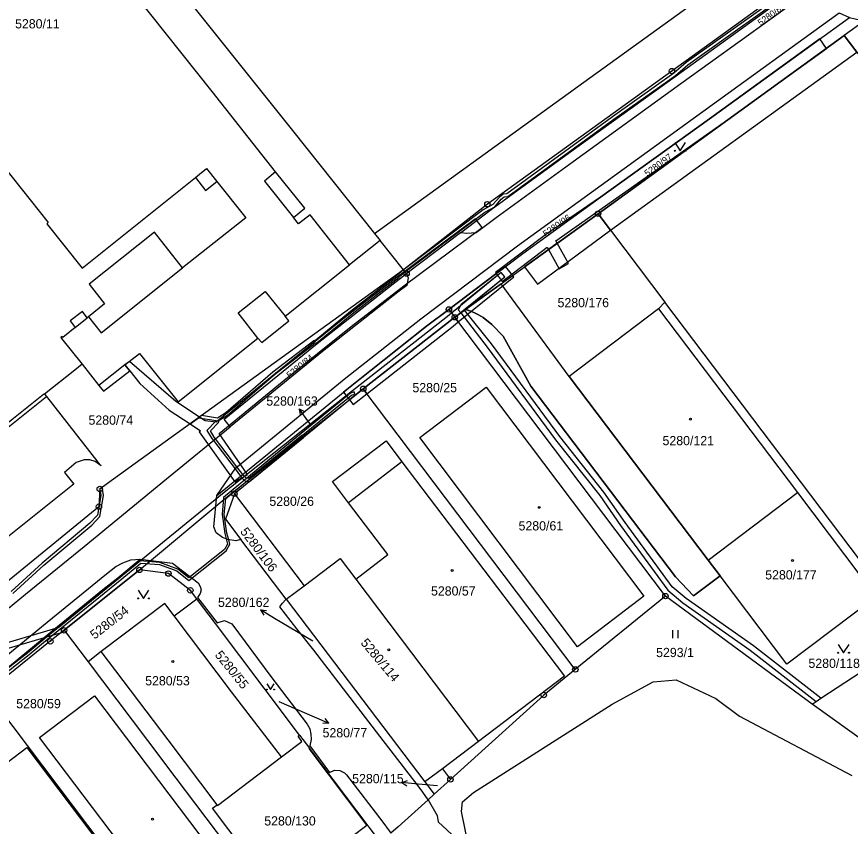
# Model space of a CAD drawing. Extents: x -644096 to -634268, y -1141430 to -1133463.
# Drawn here: x -637778.1 to -637624.4, y -1140072.9 to -1139923.7 of the extents above; entities that cross this region are included whole.
import ezdxf

# ---------------------------------------------------------------- set-up
doc = ezdxf.new("R2010")
doc.units = 0
for name, color, linetype in [('_CIVIL_CONSTRUCTION', 7, 'Continuous'), ('B_Hranice _3D', 7, 'Continuous'), ('M_Svah_Nasyp', 7, 'Continuous'), ('M_Svah_Zarez', 7, 'Continuous'), ('svrsek_osa_sjezdy', 7, 'Continuous'), ('svrsek_osa_VRT', 7, 'Continuous'), ('svrsek_popisy_VRT', 7, 'Continuous'), ('terminal_VRT', 7, 'Continuous')]:
    doc.layers.add(name, color=color, linetype=linetype)

msp = doc.modelspace()

# ---------------------------------------------------------------- linework, layer by layer
at = {"layer": '_CIVIL_CONSTRUCTION'}
for centre, radius in [((-637657.31, -1139933.74), 0.5), ((-637657.31, -1139933.74), 0.0303), ((-637691.33, -1139958.27), 0.5), ((-637691.33, -1139958.27), 0.0303), ((-637670.92, -1139960.03), 0.5), ((-637670.92, -1139960.03), 0.0303), ((-637706.23, -1139971.06), 0.5), ((-637706.23, -1139971.06), 0.0303), ((-637698.43, -1139977.67), 0.5), ((-637698.43, -1139977.67), 0.0303), ((-637697.34, -1139979.11), 0.5), ((-637697.34, -1139979.11), 0.0303), ((-637714.22, -1139992.29), 0.5), ((-637714.22, -1139992.29), 0.0303), ((-637762.79, -1140010.76), 0.5), ((-637762.79, -1140010.76), 0.0303), ((-637737.95, -1140011.63), 0.5), ((-637737.95, -1140011.63), 0.0303), ((-637762.94, -1140014.01), 0.5), ((-637762.94, -1140014.01), 0.0303), ((-637755.47, -1140025.67), 0.5), ((-637755.47, -1140025.67), 0.0303), ((-637750.13, -1140026.34), 0.5), ((-637750.13, -1140026.34), 0.0303), ((-637746.09, -1140029.43), 0.5), ((-637746.09, -1140029.43), 0.0303), ((-637658.5, -1140030.49), 0.5), ((-637658.5, -1140030.49), 0.0303), ((-637769.36, -1140036.79), 0.5), ((-637769.36, -1140036.79), 0.0303), ((-637771.9, -1140038.82), 0.5), ((-637771.9, -1140038.82), 0.0303), ((-637675.12, -1140044), 0.5), ((-637675.12, -1140044), 0.0303), ((-637680.93, -1140048.72), 0.5), ((-637680.93, -1140048.72), 0.0303), ((-637698.14, -1140064.28), 0.5), ((-637698.14, -1140064.28), 0.0303)]:
    msp.add_circle(centre, radius, dxfattribs=at)
at = {"layer": 'B_Hranice _3D'}
for points in [[(-637626.38, -1139912), (-637654.66, -1139932.19), (-637656.97, -1139934.15), (-637668.29, -1139942.19), (-637687.77, -1139956.35), (-637688.44, -1139956.44), (-637689.11, -1139956.96), (-637690.3, -1139958.33), (-637692.1, -1139959.33), (-637706.78, -1139970.37), (-637708, -1139971.4), (-637716.58, -1139978.05), (-637722.97, -1139983.33), (-637723.33, -1139983.47), (-637730.87, -1139989.25), (-637739.55, -1139996.73), (-637741.07, -1139997.68), (-637744.01, -1139997.22), (-637744.59, -1139997.64), (-637741.33, -1139998.14), (-637741.36, -1139998.24), (-637743.02, -1139999.96), (-637742.11, -1140001.47), (-637741.85, -1140001.82), (-637737.85, -1140007.05), (-637736.82, -1140008.39), (-637736.7, -1140008.55), (-637736.06, -1140009.22), (-637735.16, -1140009.36), (-637725.24, -1140001.27), (-637725.55, -1140000.88), (-637735.3, -1140008.83), (-637735.82, -1140008.75), (-637736.32, -1140008.23), (-637736.44, -1140008.07), (-637737.5, -1140006.68), (-637741.46, -1140001.5), (-637741.69, -1140001.19), (-637742.4, -1140000.04), (-637740.9, -1139998.5), (-637740.8, -1139998.1), (-637739.25, -1139997.13), (-637730.55, -1139989.63), (-637723.09, -1139983.91), (-637722.71, -1139983.77), (-637716.26, -1139978.45)], [(-637716.26, -1139978.45), (-637707.66, -1139971.76), (-637706.47, -1139970.76), (-637691.82, -1139959.75), (-637689.98, -1139958.73), (-637688.77, -1139957.32), (-637688.24, -1139956.92), (-637687.57, -1139956.83), (-637667.99, -1139942.59), (-637656.67, -1139934.55), (-637654.36, -1139932.59), (-637626.1, -1139912.4)], [(-637780.44, -1140044.91), (-637775.79, -1140041.27), (-637772.41, -1140038.42), (-637758.71, -1140027.31), (-637755.23, -1140024.4), (-637751.79, -1140024.67), (-637748.57, -1140025.86), (-637746.37, -1140027.62), (-637739.49, -1140022.17), (-637738.79, -1140020.95), (-637739.02, -1140020.11), (-637739.34, -1140018.9), (-637739.85, -1140015.44), (-637739.57, -1140012.52), (-637729.09, -1140003.85), (-637716.38, -1139993.45), (-637715.78, -1139993.26), (-637715.9, -1139992.88), (-637716.58, -1139993.09), (-637729.35, -1140003.55), (-637739.95, -1140012.32), (-637740.25, -1140015.46), (-637739.74, -1140018.98), (-637739.4, -1140020.21), (-637739.21, -1140020.89), (-637739.79, -1140021.91), (-637746.37, -1140027.1), (-637748.37, -1140025.5), (-637751.71, -1140024.27), (-637755.37, -1140023.98), (-637758.97, -1140027.01), (-637772.67, -1140038.12), (-637776.05, -1140040.95), (-637780.7, -1140044.59)], [(-637778.79, -1140030.04), (-637773.09, -1140024.82), (-637764.26, -1140017.4), (-637762.75, -1140015.82), (-637762.08, -1140011.97), (-637762.34, -1140010.44), (-637762.79, -1140010.76), (-637762.58, -1140011.97), (-637763.21, -1140015.58), (-637764.6, -1140017.04), (-637773.41, -1140024.44), (-637779.11, -1140029.66)]]:
    msp.add_lwpolyline(points, dxfattribs=at)
for points in [[(-637625.55, -1139927.19), (-637670.92, -1139960.03), (-637668.61, -1139963.08), (-637623.24, -1139930.24)], [(-637689.82, -1139970.89), (-637689.69, -1139971.06), (-637688.6, -1139972.49), (-637680.34, -1139966.2), (-637680.09, -1139966.65), (-637678.46, -1139965.47), (-637678.72, -1139965), (-637646.61, -1139942.44), (-637628.82, -1139929.56), (-637630.04, -1139927.83), (-637650.39, -1139942.52), (-637670.45, -1139957), (-637680.62, -1139963.89)], [(-637744.4, -1139997.51), (-637746.14, -1139998.76), (-637744.22, -1140000.03), (-637744.48, -1140000.22), (-637737.9, -1140009.44), (-637735.53, -1140008.08), (-637740.78, -1140000.55), (-637729.15, -1139991), (-637716.42, -1139980.8), (-637706.75, -1139973.33), (-637692.32, -1139962.59), (-637693.52, -1139960.99), (-637707.97, -1139971.75), (-637717.64, -1139979.22), (-637730.41, -1139989.46), (-637741.34, -1139998.41), (-637743.38, -1139998.19)], [(-637684.47, -1139969.81), (-637682.11, -1139973.02), (-637668.61, -1139963.08), (-637670.92, -1139960.03)], [(-637678.46, -1139965.47), (-637680.09, -1139966.65), (-637678.11, -1139970.19), (-637676.37, -1139969.21)], [(-637687.97, -1139969.76), (-637698.43, -1139977.67), (-637702.53, -1139980.77), (-637717.86, -1139992.91), (-637716.74, -1139994.34), (-637714.22, -1139992.29), (-637697.34, -1139979.11), (-637696.7, -1139979.95), (-637686.43, -1139971.67), (-637686.66, -1139971.39)], [(-637799.89, -1140046.07), (-637769.87, -1140037.2), (-637769.36, -1140036.79), (-637755.47, -1140025.67), (-637739.54, -1140012.41), (-637714.22, -1139992.29), (-637697.34, -1139979.11), (-637688.13, -1139971.63), (-637688.81, -1139970.89), (-637698.96, -1139979.2), (-637716.21, -1139992.69), (-637740.16, -1140011.63), (-637770.35, -1140036.3), (-637800.57, -1140045.22)], [(-637696.19, -1139976.76), (-637696.69, -1139977.75), (-637696.25, -1139978.32), (-637695.54, -1139977.81), (-637695.57, -1139977.77), (-637688.13, -1139971.63), (-637688.81, -1139970.89)], [(-637695.37, -1139977.69), (-637694.77, -1139977.86), (-637693.85, -1139978.23), (-637692.97, -1139978.64), (-637692.09, -1139979.15), (-637690.53, -1139980.42), (-637688.41, -1139982.57), (-637683.3, -1139991.78), (-637656.67, -1140026.92), (-637653.33, -1140030.42), (-637648.43, -1140026.77), (-637650.63, -1140023.86), (-637676.25, -1139990.02), (-637688.77, -1139972.92)], [(-637696.25, -1139978.32), (-637691.36, -1139984.62), (-637678.75, -1140001.69), (-637670.63, -1140011.94), (-637666.8, -1140017.46), (-637658.05, -1140029.4), (-637655.27, -1140031.76), (-637642.87, -1140040.47), (-637630.74, -1140049.9), (-637629.86, -1140049.32), (-637642.27, -1140039.67), (-637654.69, -1140030.94), (-637657.29, -1140028.76), (-637665.96, -1140016.9), (-637669.85, -1140011.32), (-637677.97, -1140001.07), (-637690.56, -1139984), (-637695.54, -1139977.81)], [(-637713.53, -1139993.21), (-637697.65, -1139980.72), (-637696.7, -1139979.95), (-637697.34, -1139979.11), (-637714.22, -1139992.29)], [(-637749.97, -1139996.21), (-637746.14, -1139998.76), (-637744.4, -1139997.51), (-637748.75, -1139994.61), (-637757.3, -1139987.23), (-637758.16, -1139987.9), (-637757.25, -1139989), (-637755.42, -1139991.32)], [(-637716.06, -1139995.2), (-637713.53, -1139993.21), (-637714.22, -1139992.29), (-637716.74, -1139994.34)]]:
    msp.add_lwpolyline(points, close=True, dxfattribs=at)
at = {"layer": 'M_Svah_Nasyp'}
for p, q in [((-637744.43, -1139952.76), (-637743.11, -1139951.71)), ((-637743.11, -1139951.71), (-637741.23, -1139954.12)), ((-637745.16, -1139953.36), (-637744.43, -1139952.76)), ((-637730.36, -1139952.34), (-637732.44, -1139954)), ((-637732.44, -1139954), (-637727.06, -1139960.74)), ((-637762.5, -1139981.97), (-637747.51, -1139969.98)), ((-637737.29, -1139978.29), (-637732.29, -1139974.35)), ((-637732.29, -1139974.35), (-637728.62, -1139978.92)), ((-637767.34, -1139981.01), (-637765.08, -1139979.22)), ((-637764.84, -1139979.04), (-637762.5, -1139981.97)), ((-637733.63, -1139982.94), (-637737.29, -1139978.29)), ((-637758.16, -1139987.9), (-637762.93, -1139991.7)), ((-637772.99, -1139993.25), (-637772.61, -1139993.74)), ((-637707.08, -1140005.77), (-637716.95, -1140013.28))]:
    msp.add_line(p, q, dxfattribs=at)
at = {"layer": 'M_Svah_Zarez'}
for centre in [(-637653.91, -1139997.87), (-637681.76, -1140014.14), (-637635.09, -1140023.92), (-637697.84, -1140025.79), (-637709.52, -1140040.39), (-637749.32, -1140042.55), (-637753.07, -1140071.59)]:
    msp.add_circle(centre, 0.175, dxfattribs=at)
at = {"layer": 'svrsek_osa_sjezdy'}
for p, q in [((-637657.14, -1140038.26), (-637657.14, -1140036.76)), ((-637656.14, -1140038.26), (-637656.14, -1140036.76))]:
    msp.add_line(p, q, dxfattribs=at)
for points in [[(-637656.79, -1139946.92), (-637655.79, -1139948.42), (-637654.79, -1139946.92)], [(-637755.72, -1140029.42), (-637754.72, -1140030.92), (-637753.72, -1140029.42)], [(-637626.66, -1140039.43), (-637625.66, -1140040.93), (-637624.66, -1140039.43)], [(-637732, -1140046.68), (-637731.32, -1140047.7), (-637730.64, -1140046.68)]]:
    msp.add_lwpolyline(points, dxfattribs=at)
for centre, radius in [((-637656.79, -1139948.42), 0.1), ((-637654.79, -1139948.42), 0.1), ((-637755.72, -1140030.92), 0.1), ((-637753.72, -1140030.92), 0.1), ((-637626.66, -1140040.93), 0.1), ((-637624.66, -1140040.93), 0.1), ((-637732, -1140047.7), 0.068), ((-637730.64, -1140047.7), 0.068)]:
    msp.add_circle(centre, radius, dxfattribs=at)
at = {"layer": 'svrsek_popisy_VRT'}
for p, q in [((-637724.26, -1139998.41), (-637726.02, -1139995.98)), ((-637726.02, -1139995.98), (-637725.03, -1139996.5)), ((-637726.02, -1139995.98), (-637725.84, -1139997.09)), ((-637724, -1139998.77), (-637724.26, -1139998.41)), ((-637730.56, -1140034.59), (-637733.13, -1140033.04)), ((-637733.13, -1140033.04), (-637732.02, -1140033.13)), ((-637733.13, -1140033.04), (-637732.53, -1140033.99)), ((-637723.49, -1140038.8), (-637730.56, -1140034.59)), ((-637729.75, -1140049.94), (-637723.29, -1140052.71)), ((-637723.29, -1140052.71), (-637720.53, -1140053.88)), ((-637720.53, -1140053.88), (-637721.25, -1140053.03)), ((-637720.53, -1140053.88), (-637721.65, -1140053.95)), ((-637707.11, -1140064.86), (-637706.07, -1140064.45)), ((-637704.12, -1140065.12), (-637707.11, -1140064.86)), ((-637707.11, -1140064.86), (-637706.16, -1140065.45)), ((-637700.53, -1140065.43), (-637704.12, -1140065.12))]:
    msp.add_line(p, q, dxfattribs=at)
at = {"layer": 'terminal_VRT'}
for p, q in [((-637621.84, -1139924.51), (-637625.55, -1139927.19)), ((-637670.92, -1139960.03), (-637625.55, -1139927.19)), ((-637625.55, -1139927.19), (-637612.98, -1139943.8)), ((-637695.37, -1139977.69), (-637670.92, -1139960.03)), ((-637670.92, -1139960.03), (-637658.61, -1139976.31)), ((-637712.12, -1139963.68), (-637711.11, -1139964.94)), ((-637711.11, -1139964.94), (-637716.72, -1139969.42)), ((-637706.78, -1139970.37), (-637711.11, -1139964.94)), ((-637706.23, -1139971.06), (-637706.78, -1139970.37)), ((-637658.61, -1139976.31), (-637659.77, -1139977.56)), ((-637612.18, -1140037.72), (-637658.61, -1139976.31)), ((-637698.43, -1139977.67), (-637697.34, -1139979.11)), ((-637697.34, -1139979.11), (-637695.37, -1139977.69)), ((-637659.77, -1139977.56), (-637634.18, -1140011.4)), ((-637697.34, -1139979.11), (-637714.22, -1139992.29)), ((-637658.5, -1140030.49), (-637697.34, -1139979.11)), ((-637714.22, -1139992.29), (-637737.95, -1140011.63)), ((-637675.12, -1140044), (-637714.22, -1139992.29)), ((-637737.95, -1140011.63), (-637725.13, -1140028.58)), ((-637650.63, -1140023.86), (-637634.18, -1140011.4)), ((-637728.43, -1140031.07), (-637736.81, -1140020.03)), ((-637650.63, -1140023.86), (-637648.43, -1140026.77)), ((-637715.6, -1140027.34), (-637692.94, -1140057.3)), ((-637728.43, -1140031.07), (-637725.13, -1140028.58)), ((-637749.1, -1140034.14), (-637744.91, -1140030.99)), ((-637728.43, -1140031.07), (-637702.88, -1140064.74)), ((-637658.5, -1140030.49), (-637675.12, -1140044)), ((-637631.47, -1140050.38), (-637658.5, -1140030.49)), ((-637769.36, -1140036.79), (-637764.95, -1140042.62)), ((-637629.86, -1140049.32), (-637612.18, -1140037.72)), ((-637762.51, -1140040.68), (-637764.95, -1140042.62)), ((-637783.61, -1140048.2), (-637742.13, -1140103.04)), ((-637613.75, -1140063.13), (-637631.47, -1140050.38)), ((-637725.94, -1140056.09), (-637724.13, -1140058.48)), ((-637692.94, -1140057.3), (-637699.63, -1140062.31)), ((-637711.01, -1140075.83), (-637724.13, -1140058.48)), ((-637699.63, -1140062.31), (-637702.88, -1140064.74)), ((-637699.63, -1140062.31), (-637698.14, -1140064.28)), ((-637698.14, -1140064.28), (-637701.16, -1140067.01)), ((-637702.88, -1140064.74), (-637701.16, -1140067.01)), ((-637701.16, -1140067.01), (-637702.26, -1140068.01))]:
    msp.add_line(p, q, dxfattribs=at)
for points in [[(-637563.31, -1139859.73), (-637606.05, -1139890.66), (-637603.12, -1139894.71), (-637624.44, -1139910), (-637657.31, -1139933.74), (-637691.33, -1139958.27), (-637706.78, -1139970.37)], [(-637785.99, -1139871.17), (-637767.92, -1139893.81), (-637748.41, -1139918.24), (-637727.28, -1139944.7), (-637712.12, -1139963.68)], [(-637716.72, -1139969.42), (-637724.03, -1139960.26), (-637726.12, -1139961.91), (-637727.06, -1139960.74), (-637724.96, -1139959), (-637730.36, -1139952.34), (-637742.05, -1139937.53), (-637787.38, -1139880.71), (-637793.07, -1139885.25), (-637793.55, -1139884.78), (-637787.97, -1139880.31), (-637792.06, -1139875.21)], [(-637696.28, -1139963.54), (-637690.61, -1139959.25), (-637674.44, -1139947.46), (-637656.73, -1139934.73), (-637623.8, -1139910.91), (-637590.73, -1139887.03), (-637578.64, -1139878.33)], [(-637578.64, -1139878.33), (-637578.74, -1139879.67), (-637579.14, -1139880.88), (-637589.62, -1139888.43), (-637622.83, -1139912.45), (-637655.64, -1139936.08), (-637675.49, -1139950.48), (-637689.7, -1139960.76), (-637693.39, -1139963.56), (-637695.12, -1139963.7), (-637696.28, -1139963.54)], [(-637712.12, -1139963.68), (-637673.58, -1139935.78), (-637648.87, -1139917.91), (-637605.89, -1139886.8), (-637610.08, -1139881.37), (-637611.46, -1139878.83)], [(-637741.21, -1140011.97), (-637737.73, -1140006.87), (-637717.41, -1139990.27), (-637703.62, -1139979.41), (-637685.77, -1139965.92), (-637672.15, -1139956.04), (-637651.6, -1139941.17), (-637626.45, -1139923.02), (-637624.56, -1139923.88)], [(-637698.43, -1139977.67), (-637684.78, -1139967.35), (-637670.45, -1139957), (-637650.39, -1139942.52), (-637624.56, -1139923.88)], [(-637624.56, -1139923.88), (-637622.49, -1139924.35), (-637621.84, -1139924.51)], [(-637787.32, -1139942.88), (-637772.31, -1139961.66), (-637772.55, -1139961.92), (-637766.05, -1139970.07), (-637745.16, -1139953.36), (-637743.28, -1139955.72), (-637741.23, -1139954.12), (-637735.88, -1139960.76), (-637747.51, -1139969.98), (-637752.69, -1139963.41), (-637764.76, -1139972.98), (-637761.89, -1139976.63), (-637764.84, -1139979.04), (-637765.08, -1139979.22), (-637765.98, -1139978.02), (-637768.26, -1139979.79), (-637767.34, -1139981.01), (-637769.59, -1139982.82), (-637769.7, -1139982.68), (-637769.94, -1139982.86), (-637769.85, -1139983), (-637766.06, -1139987.77)], [(-637696.28, -1139963.54), (-637706.12, -1139970.98), (-637706.23, -1139971.06)], [(-637801.31, -1140015.8), (-637800.91, -1140016.32), (-637772.61, -1139993.74), (-637763.13, -1140005.8), (-637762.54, -1140006.46), (-637763.62, -1140005.68), (-637764.62, -1140005.39), (-637765.66, -1140005.36), (-637767.13, -1140005.88), (-637769.28, -1140007.73), (-637767.54, -1140009.89), (-637767.79, -1140010.06), (-637799.19, -1140035.12), (-637808.83, -1140023.02), (-637812.28, -1140018.54), (-637839.95, -1139983.66), (-637852.33, -1139968.09)], [(-637706.78, -1139970.37), (-637752.95, -1140003.67), (-637761.33, -1140009.71), (-637762.79, -1140010.76), (-637762.94, -1140014.01), (-637800.78, -1140044.95)], [(-637766.06, -1139987.77), (-637762.93, -1139991.7), (-637762.1, -1139992.71), (-637757.25, -1139989), (-637758.16, -1139987.9), (-637755.46, -1139985.79), (-637748.36, -1139994.67), (-637733.63, -1139982.94), (-637732.88, -1139983.73), (-637727.94, -1139979.76), (-637728.62, -1139978.92), (-637716.72, -1139969.42)], [(-637738.74, -1139999.28), (-637739.84, -1139997.9), (-637722.69, -1139983.97), (-637708.69, -1139972.93), (-637706.23, -1139971.06)], [(-637706.23, -1139971.06), (-637705.93, -1139971.82), (-637706.18, -1139973.24), (-637707.84, -1139974.5), (-637721.74, -1139985.44), (-637738.74, -1139999.28)], [(-637741.21, -1140011.97), (-637716.55, -1139991.84), (-637702.53, -1139980.77), (-637698.43, -1139977.67)], [(-637648.43, -1140026.77), (-637653.33, -1140030.42), (-637656.67, -1140026.92), (-637683.3, -1139991.78), (-637688.41, -1139982.57), (-637690.53, -1139980.42), (-637692.09, -1139979.15), (-637692.97, -1139978.64), (-637693.85, -1139978.23), (-637694.77, -1139977.86), (-637695.37, -1139977.69)], [(-637659.77, -1139977.56), (-637676.25, -1139990.02), (-637650.63, -1140023.86)], [(-637766.06, -1139987.77), (-637767.41, -1139988.84), (-637772.99, -1139993.25), (-637773.13, -1139993.36), (-637779.01, -1139998.01), (-637781.96, -1140000.37)], [(-637691.54, -1139992.02), (-637662.47, -1140030.52), (-637674.7, -1140039.82), (-637703.81, -1140001.26), (-637691.54, -1139992.02)], [(-637845.37, -1140086.59), (-637832.39, -1140075.95), (-637810.87, -1140058.32), (-637793.23, -1140043.88), (-637776.46, -1140030.14), (-637765.68, -1140021.35), (-637750.47, -1140008.86), (-637738.74, -1139999.28)], [(-637715.6, -1140027.34), (-637709.68, -1140022.85), (-637716.95, -1140013.28), (-637719.87, -1140009.4), (-637709.96, -1140001.85), (-637707.08, -1140005.77), (-637684.44, -1140035.61), (-637677.14, -1140045.23), (-637692.94, -1140057.3)], [(-637736.81, -1140020.03), (-637737.69, -1140020.31), (-637739.23, -1140020.03), (-637740.17, -1140019.67), (-637741.3, -1140018.83), (-637741.78, -1140017.73), (-637741.21, -1140011.97)], [(-637737.95, -1140011.63), (-637739.63, -1140016.31), (-637736.81, -1140020.03)], [(-637634.18, -1140011.4), (-637619.69, -1140030.61), (-637636.14, -1140043.05), (-637648.43, -1140026.77)], [(-637817.35, -1140072.05), (-637807.11, -1140063.64), (-637789.18, -1140048.96), (-637772.5, -1140035.3), (-637761.56, -1140026.38), (-637759.83, -1140025.01), (-637758.55, -1140024.34), (-637757.04, -1140023.82), (-637755.35, -1140023.67)], [(-637817.35, -1140072.05), (-637816.23, -1140073.56), (-637805.85, -1140065.05), (-637788.02, -1140050.44), (-637771.25, -1140036.65), (-637762.25, -1140029.27), (-637759.48, -1140027.1), (-637755.35, -1140023.67)], [(-637755.35, -1140023.67), (-637749.35, -1140024.42), (-637744.64, -1140028.02), (-637744.26, -1140028.71), (-637744.09, -1140029.36), (-637744.26, -1140030.01), (-637744.77, -1140030.73), (-637741.17, -1140035.4), (-637739.81, -1140034.99), (-637738.41, -1140035.62), (-637731.25, -1140045.32), (-637724.55, -1140054.08), (-637724.09, -1140054.96), (-637723.86, -1140055.92), (-637723.81, -1140056.92), (-637724.07, -1140058.08), (-637720.43, -1140062.99), (-637719.53, -1140062.58), (-637718.55, -1140062.62), (-637717.68, -1140063.07), (-637717.32, -1140063.44), (-637710.62, -1140072.15), (-637709.44, -1140073.76), (-637709.14, -1140074.2)], [(-637725.13, -1140028.58), (-637718.46, -1140023.56), (-637715.6, -1140027.34)], [(-637744.91, -1140030.99), (-637746.09, -1140029.43), (-637750.13, -1140026.34), (-637755.47, -1140025.67), (-637769.36, -1140036.79)], [(-637749.1, -1140034.14), (-637750.81, -1140031.88), (-637762.51, -1140040.68)], [(-637725.94, -1140056.09), (-637732.47, -1140047.45), (-637741.48, -1140035.52), (-637744.78, -1140031.16), (-637744.91, -1140030.99)], [(-637702.26, -1140068.01), (-637703.23, -1140066.63), (-637704.1, -1140065.43), (-637711.15, -1140056.33), (-637723.35, -1140040.47), (-637726.44, -1140036.54), (-637729.58, -1140032.47), (-637729.19, -1140031.83), (-637728.43, -1140031.07)], [(-637729.29, -1140060.1), (-637738.49, -1140048.14), (-637749.1, -1140034.14)], [(-637769.36, -1140036.79), (-637771.9, -1140038.82), (-637783.61, -1140048.2)], [(-637741.17, -1140068.93), (-637750.17, -1140056.99), (-637762.51, -1140040.68)], [(-637764.95, -1140042.62), (-637759.67, -1140049.6), (-637751.15, -1140060.87), (-637750.67, -1140061.5), (-637728.34, -1140091.03)], [(-637675.12, -1140044), (-637680.93, -1140048.72), (-637698.14, -1140064.28)], [(-637702.26, -1140068.01), (-637700.61, -1140070.93), (-637700.39, -1140072.11), (-637694.64, -1140077.44), (-637696.09, -1140070.18), (-637695.9, -1140068.42), (-637693.88, -1140066.68), (-637668.35, -1140050.42), (-637660.75, -1140046.26), (-637656.5, -1140045.9), (-637649.2, -1140049.37), (-637644.85, -1140052.63), (-637624.17, -1140063.57)], [(-637744.59, -1140095.27), (-637773.88, -1140056.54), (-637763.73, -1140048.86), (-637734.44, -1140087.62), (-637744.59, -1140095.27)], [(-637631.47, -1140050.38), (-637630.74, -1140049.9), (-637629.86, -1140049.32)], [(-637729.29, -1140060.1), (-637725.53, -1140057.27), (-637726.23, -1140056.3), (-637725.94, -1140056.09)], [(-637786.36, -1140066.04), (-637776.22, -1140058.38), (-637746.95, -1140097.15), (-637757.1, -1140104.82), (-637786.36, -1140066.04)], [(-637724.13, -1140058.48), (-637724.25, -1140058.58), (-637713.56, -1140072.76), (-637730.14, -1140085.32), (-637742.03, -1140069.58), (-637741.17, -1140068.93)], [(-637741.17, -1140068.93), (-637741.08, -1140069.05), (-637729.29, -1140060.1)], [(-637702.26, -1140068.01), (-637707.79, -1140073.03), (-637709.14, -1140074.2)]]:
    msp.add_lwpolyline(points, dxfattribs=at)

# ---------------------------------------------------------------- texts
at = {"layer": 'svrsek_osa_VRT'}
for s, height, rotation, p in [('5280/85', 1.2, 36, (-637640.96, -1139925.46)), ('5280/97', 1.2, 36, (-637661.85, -1139953.22)), ('5280/96', 1.2, 35, (-637680.57, -1139964.36)), ('5280/84', 1.2, 39, (-637727.77, -1139990.42)), ('5280/106', 1.7, 307, (-637736.99, -1140018.64)), ('5280/54', 1.7, 38, (-637763.74, -1140038.53)), ('5280/114', 1.7, 310, (-637714.79, -1140039.17)), ('5280/55', 1.7, 309, (-637741.67, -1140041.39))]:
    msp.add_text(s, height=height, rotation=rotation, dxfattribs=at).set_placement(p)
for s, p in [('5280/11', (-637778.4, -1139925.88)), ('5280/176', (-637678.39, -1139977.26)), ('5280/25', (-637705.15, -1139992.93)), ('5280/163', (-637732.08, -1139995.39)), ('5280/74', (-637764.86, -1139998.91)), ('5280/121', (-637659.04, -1140002.69)), ('5280/26', (-637731.52, -1140013.86)), ('5280/61', (-637685.58, -1140018.39)), ('5280/177', (-637640.11, -1140027.42)), ('5280/57', (-637701.72, -1140030.39)), ('5280/162', (-637740.99, -1140032.48)), ('5293/1', (-637660.22, -1140041.73)), ('5280/118', (-637632.14, -1140043.72)), ('5280/53', (-637754.41, -1140046.94)), ('5280/59', (-637778.18, -1140051.15)), ('5280/77', (-637721.71, -1140056.52)), ('5280/115', (-637716.25, -1140064.97)), ('5280/130', (-637732.46, -1140072.76))]:
    msp.add_text(s, height=1.7, dxfattribs=at).set_placement(p)

doc.saveas('drawing.dxf')
